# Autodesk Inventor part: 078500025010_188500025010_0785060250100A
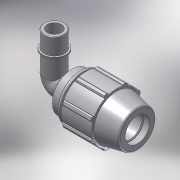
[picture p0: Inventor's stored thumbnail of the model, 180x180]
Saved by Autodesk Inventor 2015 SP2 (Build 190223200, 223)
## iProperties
Created: 2017-02
Part Number: 078500025010_188500025010_0785060250100A
Material: PVC-Piping
Description: PLASSON 90° ELBOW MALE ADAPTOR 25-1"
Document SubType Name: Modeling
Designer: KIM
Mass: 92.6774 g
Surface Area: 199.44 cm^2
Volume: 66.1981 cm^3
Density: 1.4 g/cm^3
Appearance: Smooth - White
Author: KIM
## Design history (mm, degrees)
derived "07850.ipt"
feature "Solid1::07850.ipt"
tag "TaggingFeature1"
body "Solid1"
other parameters: "d2" = 25, "d4" = 7.5, "d5" = 22.5, "d7" = 54, "d9" = 12.85714, "d11" = 3, "d13" = 120 deg, "d14" = 37.5, "d15" = 12 deg, "d16" = 46.98, "d18" = 1.25, "d19" = 35 deg, "d20" = 17.5 deg, "d21" = 50.22, "d23" = 0, "d25" = 360 deg, "d27" = 1.08, "d33" = 0.5, "d42" = 33.3, "d43" = 1.62, "d46" = 0.75, "d68" = 3, "d72" = 54, "d73" = 33.249, "d75" = 38.23635, "d76" = 23.2743, "d77" = 22, "d79" = 13.2996, "d80" = 0.99747, "d83" = 0, "d84" = 0, "d91" = 40.5, "d93" = 58, "d94" = 33.249, "d95" = 23.2743, "d96" = 9, "d97" = 50 deg, "d_" = 25, "E_" = 54, "l_" = 58, "A_1" = 54, "R_" = 33.249
